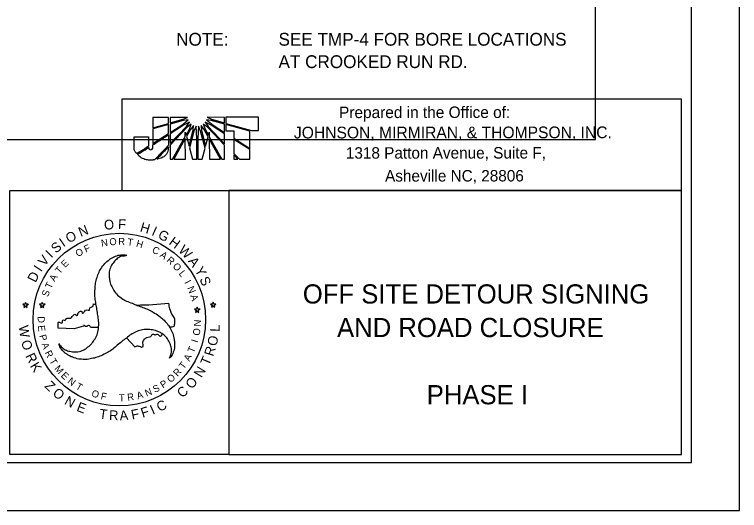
# Model space of a CAD drawing. Extents: x 1613335 to 1618399, y 897277 to 901877.
# Drawn here: x 1617265 to 1618399, y 898577 to 899353 of the extents above; entities that cross this region are included whole.
import ezdxf

# ---------------------------------------------------------------- set-up
doc = ezdxf.new("R2010")
doc.units = 0
for name, color, linetype in [('Default', 7, 'Continuous'), ('DEV BORDER CELL', 7, 'Continuous'), ('DEV DOT SWIRL SEAL CELL', 7, 'Continuous'), ('Scratch_Level_0', 7, 'Continuous'), ('Sheet Plan CELL', 7, 'Continuous'), ('Sheet Plot Border Outside CELL', 7, 'Continuous'), ('Sheet Title CELL', 7, 'Continuous'), ('Text', 7, 'Continuous'), ('WZ INSETA CELL', 7, 'Continuous')]:
    doc.layers.add(name, color=color, linetype=linetype)

msp = doc.modelspace()

# ---------------------------------------------------------------- linework, layer by layer
at = {"layer": 'Default'}
for p, q in [((1617505.8, 899191.7), (1617481.5, 899191.7)), ((1617481.5, 899191.7), (1617481.6, 899175.6)), ((1617505.8, 899182.3), (1617505.8, 899191.7)), ((1617535.7, 899191.8), (1617508.3, 899191.8)), ((1617508.3, 899191.8), (1617508.4, 899183.1)), ((1617528.7, 899188.7), (1617535.7, 899191.8)), ((1617593.6, 899191.8), (1617566.6, 899191.9)), ((1617566.6, 899191.9), (1617573.4, 899188.7)), ((1617593.6, 899183), (1617593.6, 899191.8)), ((1617646.5, 899191.9), (1617595.4, 899191.9)), ((1617595.4, 899191.9), (1617595.5, 899182.5)), ((1617646.5, 899171), (1617646.5, 899191.9)), ((1617481.6, 899175.6), (1617505.8, 899182.3)), ((1617505.8, 899180.5), (1617481.6, 899173.7)), ((1617505.8, 899166.5), (1617505.8, 899180.5)), ((1617508.4, 899183.1), (1617528.7, 899188.7)), ((1617528.7, 899186.9), (1617508.4, 899181.2)), ((1617508.4, 899181.2), (1617508.4, 899168.1)), ((1617508.4, 899168.1), (1617526.6, 899179.6)), ((1617526.6, 899179.6), (1617536.7, 899187.8)), ((1617536.7, 899187.8), (1617528.7, 899186.9)), ((1617538.7, 899184.1), (1617529.4, 899179.4)), ((1617534, 899177.5), (1617538.7, 899184.1)), ((1617541.5, 899181.1), (1617535, 899176.2)), ((1617538.5, 899173.4), (1617541.5, 899181.1)), ((1617560.3, 899181.2), (1617563.3, 899173.4)), ((1617566.8, 899176.2), (1617560.3, 899181.2)), ((1617563.1, 899184.1), (1617567.8, 899177.4)), ((1617572.5, 899179.4), (1617563.1, 899184.1)), ((1617565.3, 899187.9), (1617575.5, 899179.5)), ((1617572.8, 899186.9), (1617565.3, 899187.9)), ((1617593.6, 899181.2), (1617572.8, 899186.9)), ((1617573.4, 899188.7), (1617593.6, 899183)), ((1617593.4, 899168.3), (1617593.6, 899181.2)), ((1617595.5, 899182.5), (1617595.5, 899182.2)), ((1617595.5, 899182.2), (1617635.7, 899171)), ((1617595.5, 899180.8), (1617595.5, 899180.6)), ((1617633.1, 899170.1), (1617595.5, 899180.8)), ((1617595.5, 899180.6), (1617595.5, 899170.8)), ((1617481.6, 899173.7), (1617481.6, 899151.1)), ((1617529.4, 899179.4), (1617508.4, 899166)), ((1617508.4, 899150.8), (1617534, 899177.5)), ((1617535, 899176.2), (1617508.4, 899148.2)), ((1617532.2, 899162.1), (1617532.2, 899168.5)), ((1617532.2, 899168.5), (1617533.4, 899164.1)), ((1617533.4, 899164.1), (1617538.5, 899173.4)), ((1617540.2, 899172.8), (1617534.1, 899161.8)), ((1617538, 899147.2), (1617544.3, 899171.5)), ((1617545.6, 899170.1), (1617538.8, 899143.9)), ((1617545, 899179), (1617540.2, 899172.8)), ((1617544.3, 899171.5), (1617545, 899179)), ((1617549, 899177.9), (1617545.6, 899170.1)), ((1617550, 899158.7), (1617549, 899177.9)), ((1617553, 899177.9), (1617551.7, 899158.7)), ((1617556.2, 899170.1), (1617553, 899177.9)), ((1617563.2, 899143.5), (1617556.2, 899170.1)), ((1617556.9, 899179), (1617557.7, 899171.2)), ((1617561.6, 899172.8), (1617556.9, 899179)), ((1617557.7, 899171.2), (1617564, 899146.7)), ((1617567.9, 899161.4), (1617561.6, 899172.8)), ((1617563.3, 899173.4), (1617568.5, 899163.7)), ((1617593.4, 899148.1), (1617566.8, 899176.2)), ((1617567.8, 899177.4), (1617593.4, 899150.6)), ((1617568.5, 899163.7), (1617569.7, 899168.5)), ((1617569.7, 899168.5), (1617569.7, 899161.4)), ((1617593.4, 899166.2), (1617572.5, 899179.4)), ((1617575.5, 899179.5), (1617593.4, 899168.3)), ((1617595.5, 899170.8), (1617607.9, 899170.9)), ((1617607.9, 899170.9), (1617607.9, 899159.2)), ((1617633.1, 899143.3), (1617633.1, 899170.1)), ((1617635.7, 899171), (1617646.5, 899171)), ((1617481.6, 899151.1), (1617505.8, 899166.5)), ((1617508.4, 899166), (1617508.4, 899150.8)), ((1617512.4, 899126.2), (1617532.2, 899162.1)), ((1617532.2, 899158.6), (1617514.3, 899126.2)), ((1617532.4, 899126.2), (1617532.2, 899158.6)), ((1617534.1, 899161.8), (1617538, 899147.2)), ((1617550.1, 899126.4), (1617550, 899158.7)), ((1617551.7, 899158.7), (1617551.8, 899126.4)), ((1617564, 899146.7), (1617567.9, 899161.4)), ((1617569.7, 899161.4), (1617589.2, 899126.3)), ((1617587.2, 899126.4), (1617569.7, 899158)), ((1617569.7, 899158), (1617569.8, 899126.4)), ((1617593.4, 899150.6), (1617593.4, 899166.2)), ((1617607.9, 899159.2), (1617633.1, 899143.3)), ((1617607.9, 899157.2), (1617608, 899135.5)), ((1617633.1, 899141.4), (1617607.9, 899157.2)), ((1617508.4, 899148.2), (1617508.4, 899126.2)), ((1617593.5, 899126.3), (1617593.4, 899148.1)), ((1617538.8, 899143.9), (1617543.4, 899126.4)), ((1617558.5, 899126.4), (1617563.2, 899143.5)), ((1617608, 899135.5), (1617616.7, 899126.3)), ((1617633.1, 899126.3), (1617633.1, 899141.4)), ((1617508.4, 899126.2), (1617512.4, 899126.2)), ((1617514.3, 899126.2), (1617532.4, 899126.2)), ((1617543.4, 899126.4), (1617550.1, 899126.4)), ((1617551.8, 899126.4), (1617558.5, 899126.4)), ((1617569.8, 899126.4), (1617587.2, 899126.4)), ((1617589.2, 899126.3), (1617593.5, 899126.3)), ((1617614.3, 899126.3), (1617608, 899133.1)), ((1617608, 899133.1), (1617608, 899126.3)), ((1617608, 899126.3), (1617614.3, 899126.3)), ((1617616.7, 899126.3), (1617633.1, 899126.3))]:
    msp.add_line(p, q, dxfattribs=at)
for points in [[(1617481.6, 899175.6), (1617505.8, 899182.3), (1617505.8, 899191.7), (1617481.5, 899191.7), (1617481.6, 899175.6)], [(1617528.7, 899188.7), (1617535.7, 899191.8), (1617508.3, 899191.8), (1617508.4, 899183.1), (1617528.7, 899188.7)], [(1617573.4, 899188.7), (1617593.6, 899183), (1617593.6, 899191.8), (1617566.6, 899191.9), (1617573.4, 899188.7)], [(1617481.6, 899151.1), (1617505.8, 899166.5), (1617505.8, 899180.5), (1617481.6, 899173.7), (1617481.6, 899151.1)], [(1617508.4, 899181.2), (1617508.4, 899168.1), (1617526.6, 899179.6), (1617536.7, 899187.8), (1617528.7, 899186.9), (1617508.4, 899181.2)], [(1617508.4, 899166), (1617508.4, 899150.8), (1617534, 899177.5), (1617538.7, 899184.1), (1617529.4, 899179.4), (1617508.4, 899166)], [(1617541.5, 899181.1), (1617535, 899176.2), (1617508.4, 899148.2), (1617508.4, 899126.2), (1617512.4, 899126.2), (1617532.2, 899162.1), (1617532.2, 899168.5), (1617533.4, 899164.1), (1617538.5, 899173.4), (1617541.5, 899181.1)], [(1617560.3, 899181.2), (1617563.3, 899173.4), (1617568.5, 899163.7), (1617569.7, 899168.5), (1617569.7, 899161.4), (1617589.2, 899126.3), (1617593.5, 899126.3), (1617593.4, 899148.1), (1617566.8, 899176.2), (1617560.3, 899181.2)], [(1617563.1, 899184.1), (1617567.8, 899177.4), (1617593.4, 899150.6), (1617593.4, 899166.2), (1617572.5, 899179.4), (1617563.1, 899184.1)], [(1617565.3, 899187.9), (1617575.5, 899179.5), (1617593.4, 899168.3), (1617593.6, 899181.2), (1617572.8, 899186.9), (1617565.3, 899187.9)], [(1617595.5, 899180.8), (1617595.5, 899180.6), (1617595.5, 899170.8), (1617607.9, 899170.9), (1617607.9, 899159.2), (1617633.1, 899143.3), (1617633.1, 899170.1), (1617595.5, 899180.8)], [(1617545, 899179), (1617540.2, 899172.8), (1617534.1, 899161.8), (1617538, 899147.2), (1617544.3, 899171.5), (1617545, 899179)], [(1617545.6, 899170.1), (1617538.8, 899143.9), (1617543.4, 899126.4), (1617550.1, 899126.4), (1617550, 899158.7), (1617549, 899177.9), (1617545.6, 899170.1)], [(1617553, 899177.9), (1617551.7, 899158.7), (1617551.8, 899126.4), (1617558.5, 899126.4), (1617563.2, 899143.5), (1617556.2, 899170.1), (1617553, 899177.9)], [(1617556.9, 899179), (1617557.7, 899171.2), (1617564, 899146.7), (1617567.9, 899161.4), (1617561.6, 899172.8), (1617556.9, 899179)], [(1617514.3, 899126.2), (1617532.4, 899126.2), (1617532.2, 899158.6), (1617514.3, 899126.2)], [(1617569.8, 899126.4), (1617587.2, 899126.4), (1617569.7, 899158), (1617569.8, 899126.4)], [(1617607.9, 899157.2), (1617608, 899135.5), (1617616.7, 899126.3), (1617633.1, 899126.3), (1617633.1, 899141.4), (1617607.9, 899157.2), (1617607.9, 899157.2)], [(1617608, 899126.3), (1617608, 899126.3), (1617614.3, 899126.3), (1617608, 899133.1), (1617608, 899126.3)]]:
    msp.add_lwpolyline(points, dxfattribs=at)
for points in [[(1617474.6, 899161.5), (1617474.6, 899161.5), (1617452.1, 899161.5), (1617452.1, 899161.5), (1617452.1, 899161.5), (1617452.1, 899147.4), (1617452.1, 899147.4), (1617452.1, 899147.4), (1617452.1, 899145.9), (1617452.1, 899145.9), (1617452.1, 899141.5), (1617453.6, 899138), (1617456.1, 899135.1), (1617456.1, 899135.1), (1617474.6, 899146.3), (1617474.6, 899146.6), (1617474.6, 899146.6), (1617474.6, 899161.5), (1617474.6, 899161.5)], [(1617474.6, 899161.5), (1617474.6, 899161.5), (1617452.1, 899161.5), (1617452.1, 899161.5), (1617452.1, 899161.5), (1617452.1, 899147.4), (1617452.1, 899147.4), (1617452.1, 899147.4), (1617452.1, 899145.9), (1617452.1, 899145.9), (1617452.1, 899141.5), (1617453.6, 899138), (1617456.1, 899135.1), (1617456.1, 899135.1), (1617474.6, 899146.3), (1617474.6, 899146.6), (1617474.6, 899146.6), (1617474.6, 899161.5), (1617474.6, 899161.5)], [(1617478.1, 899141.2), (1617476.7, 899141.2), (1617475.4, 899142), (1617474.9, 899144.7), (1617474.9, 899144.7), (1617457.5, 899133.9), (1617457.5, 899133.9), (1617462.8, 899128.3), (1617471.4, 899124.9), (1617478.7, 899124.9), (1617480.6, 899124.9), (1617482, 899125.1), (1617484, 899125.5), (1617484, 899125.5), (1617505.9, 899148.1), (1617505.9, 899148.1), (1617505.9, 899148.1), (1617505.8, 899164.5), (1617505.8, 899164.5), (1617505.8, 899164.5), (1617481.6, 899149), (1617481.6, 899149), (1617481.6, 899142.9), (1617480.1, 899141.2), (1617478.1, 899141.2)], [(1617478.1, 899141.2), (1617476.7, 899141.2), (1617475.4, 899142), (1617474.9, 899144.7), (1617474.9, 899144.7), (1617457.5, 899133.9), (1617457.5, 899133.9), (1617462.8, 899128.3), (1617471.4, 899124.9), (1617478.7, 899124.9), (1617480.6, 899124.9), (1617482, 899125.1), (1617484, 899125.5), (1617484, 899125.5), (1617505.9, 899148.1), (1617505.9, 899148.1), (1617505.9, 899148.1), (1617505.8, 899164.5), (1617505.8, 899164.5), (1617505.8, 899164.5), (1617481.6, 899149), (1617481.6, 899149), (1617481.6, 899142.9), (1617480.1, 899141.2), (1617478.1, 899141.2)], [(1617505.9, 899145.6), (1617505.9, 899145.6), (1617487, 899126), (1617487, 899126), (1617496.2, 899128.3), (1617505.4, 899134.5), (1617505.9, 899145.6)], [(1617505.9, 899145.6), (1617505.9, 899145.6), (1617487, 899126), (1617487, 899126), (1617496.2, 899128.3), (1617505.4, 899134.5), (1617505.9, 899145.6)]]:
    msp.add_open_spline(points, degree=3, dxfattribs=at)
at = {"layer": 'DEV BORDER CELL'}
for points in [[(1618323.6, 901802.3), (1613823.6, 901802.3), (1613823.6, 898652.3), (1618323.6, 898652.3)], [(1617258.1, 899077.6), (1617600.1, 899077.6), (1617600.1, 898665.1), (1617258.1, 898665.1)], [(1618308.1, 899077.6), (1617600.1, 899077.6), (1617600.1, 898665.1), (1618308.1, 898665.1)]]:
    msp.add_lwpolyline(points, close=True, dxfattribs=at)
at = {"layer": 'DEV DOT SWIRL SEAL CELL'}
for p, q in [((1617278.3, 898899.6), (1617280.9, 898897.7)), ((1617281.6, 898899.6), (1617278.3, 898899.6)), ((1617280.9, 898897.7), (1617280, 898894.6)), ((1617280, 898894.6), (1617282.5, 898896.5)), ((1617282.5, 898902.6), (1617281.6, 898899.6)), ((1617283.6, 898899.6), (1617282.5, 898902.6)), ((1617282.5, 898896.5), (1617285.2, 898894.6)), ((1617282.5, 898896.5), (1617285.2, 898894.6)), ((1617286.8, 898899.6), (1617283.6, 898899.6)), ((1617284.2, 898897.7), (1617286.9, 898899.6)), ((1617284.2, 898897.7), (1617286.8, 898899.6)), ((1617285.2, 898894.6), (1617284.2, 898897.7)), ((1617285.2, 898894.6), (1617284.2, 898897.7)), ((1617307.6, 898899.6), (1617304.3, 898899.6)), ((1617304.3, 898899.6), (1617307, 898897.6)), ((1617307, 898897.6), (1617306, 898894.5)), ((1617306, 898894.5), (1617308.6, 898896.4)), ((1617308.6, 898902.6), (1617307.6, 898899.6)), ((1617309.6, 898899.6), (1617308.6, 898902.6)), ((1617308.6, 898896.4), (1617311.2, 898894.5)), ((1617312.9, 898899.6), (1617309.6, 898899.6)), ((1617310.2, 898897.6), (1617312.9, 898899.6)), ((1617311.2, 898894.5), (1617310.2, 898897.6)), ((1617574.7, 898900), (1617571.5, 898900)), ((1617571.5, 898900), (1617574.1, 898898.1)), ((1617574.1, 898898.1), (1617573.2, 898895)), ((1617573.2, 898895), (1617575.7, 898896.9)), ((1617575.7, 898903), (1617574.7, 898900)), ((1617576.8, 898900), (1617575.7, 898903)), ((1617575.7, 898896.9), (1617578.3, 898895)), ((1617580, 898900), (1617576.8, 898900)), ((1617577.4, 898898.1), (1617580, 898900)), ((1617578.3, 898895), (1617577.4, 898898.1)), ((1617549.9, 898892.1), (1617546.6, 898892.1)), ((1617546.6, 898892.1), (1617549.3, 898890.2)), ((1617549.3, 898890.2), (1617548.3, 898887)), ((1617548.3, 898887), (1617550.9, 898889)), ((1617550.9, 898895.1), (1617549.9, 898892.1)), ((1617551.9, 898892.1), (1617550.9, 898895.1)), ((1617550.9, 898889), (1617553.5, 898887)), ((1617555.2, 898892.1), (1617551.9, 898892.1)), ((1617552.5, 898890.2), (1617555.2, 898892.1)), ((1617553.5, 898887), (1617552.5, 898890.2)), ((1617333.3, 898862.3), (1617333.5, 898870.2)), ((1617358.5, 898861.3), (1617333.3, 898862.3)), ((1617372.9, 898865.6), (1617358.5, 898861.3)), ((1617384, 898863.9), (1617396.6, 898863.8)), ((1617440.2, 898847), (1617453.1, 898833))]:
    msp.add_line(p, q, dxfattribs=at)
for start, end in [(265.6785, 265.9762), (271.2035, 275.3236)]:
    msp.add_arc((1617441.4, 899597.8), 699.6, start, end, dxfattribs=at)
for points in [[(1617334.5, 898837.9), (1617339.7, 898831.9), (1617346.3, 898827.7), (1617353.8, 898825.8), (1617362.2, 898825.3), (1617370.8, 898827.3), (1617376.6, 898830.2), (1617379, 898832.1), (1617383.2, 898835.4), (1617386.1, 898838.7), (1617391.1, 898845.8), (1617395, 898854.1), (1617396.6, 898863.7), (1617396.7, 898864.5), (1617396.6, 898873.5), (1617395.4, 898882.6), (1617394.1, 898891.4), (1617392.5, 898900.5), (1617391.1, 898909.5), (1617390.9, 898918.3), (1617391.5, 898928.4), (1617392.9, 898937), (1617395.7, 898945.9), (1617397.3, 898950), (1617399.3, 898953.4), (1617404.6, 898961.4), (1617411.4, 898967.8), (1617415.9, 898971.2), (1617420.2, 898973.5), (1617420.9, 898973.9), (1617429.5, 898976.6), (1617437.8, 898976.9), (1617440.7, 898976.2)], [(1617440.9, 898976.5), (1617440.7, 898976.2), (1617432.9, 898974.8), (1617425.9, 898971.1), (1617420.5, 898965.7), (1617415.9, 898958.7), (1617413.4, 898950.1), (1617413, 898943.8), (1617413.5, 898940.7), (1617414.2, 898935.4), (1617415.5, 898931.2), (1617419.2, 898923.4), (1617424.5, 898915.8), (1617432, 898909.6), (1617432.7, 898909.1), (1617440.4, 898904.7), (1617449, 898901.2), (1617457.2, 898897.9), (1617465.9, 898894.8), (1617474.4, 898891.4), (1617482.1, 898887.2), (1617490.6, 898881.7), (1617497.3, 898876.2), (1617503.6, 898869.4), (1617506.5, 898865.9), (1617508.3, 898862.4), (1617512.7, 898853.9), (1617514.7, 898844.7), (1617515.5, 898839.1), (1617515.3, 898834.2), (1617515.3, 898833.4), (1617513.3, 898824.7), (1617509.4, 898817.3), (1617507.4, 898815.2)], [(1617333.5, 898870.2), (1617333.3, 898871), (1617334.6, 898871.9), (1617338.4, 898870.3), (1617340.2, 898871.9), (1617340.1, 898873.6), (1617341.7, 898875.2), (1617344.2, 898874.7), (1617346.5, 898877.5), (1617348.6, 898878.1), (1617353.1, 898878.1), (1617358.5, 898883.5), (1617360.7, 898883.8), (1617361.3, 898882.4), (1617362.6, 898882.1), (1617365, 898886.5), (1617365.6, 898887.1), (1617369.6, 898888.8), (1617370.7, 898888), (1617371.1, 898886), (1617371.7, 898885.7), (1617373, 898886.6), (1617374.9, 898889), (1617378.3, 898890.8), (1617382.2, 898890.3), (1617382.9, 898893.5), (1617387.4, 898896.5), (1617388.4, 898898.4), (1617388.6, 898900.3)], [(1617507.2, 898864.6), (1617514.6, 898865.5), (1617515.7, 898871.4), (1617515.8, 898876.3), (1617512.7, 898881.9), (1617508.2, 898892.4), (1617506.3, 898901.3)], [(1617384, 898863.9), (1617383, 898865.8), (1617380.9, 898866.4), (1617378.1, 898865), (1617376.1, 898865.1), (1617373.8, 898866.8), (1617372.9, 898865.6)], [(1617507.4, 898815.2), (1617510, 898822.6), (1617510.4, 898830.5), (1617508.3, 898837.9), (1617504.5, 898845.4), (1617498.5, 898851.9), (1617493.2, 898855.4), (1617490.2, 898856.5), (1617485.4, 898858.6), (1617480.9, 898859.5), (1617472.4, 898860.2), (1617463.1, 898859.4), (1617454, 898856), (1617453.3, 898855.7), (1617445.6, 898851.1), (1617438.2, 898845.5), (1617431.2, 898840), (1617424.2, 898834.1), (1617417.1, 898828.3), (1617409.6, 898823.8), (1617400.6, 898819.2), (1617392.4, 898816.2), (1617383.4, 898814.2), (1617378.9, 898813.4), (1617374.9, 898813.5), (1617365.5, 898814), (1617356.4, 898816.8), (1617351.3, 898818.9), (1617347.2, 898821.6), (1617346.4, 898822), (1617339.8, 898828), (1617335.4, 898835.1), (1617334.5, 898837.9)], [(1617453.1, 898833), (1617458.2, 898834.6), (1617462.5, 898832.9), (1617464.5, 898832.6), (1617466.2, 898833.9), (1617465.7, 898840.2), (1617467.1, 898843.2), (1617474, 898848.3), (1617478.2, 898849.2), (1617481.4, 898853.1), (1617482.6, 898853), (1617484.6, 898851.9), (1617488.9, 898852.8), (1617492.4, 898850), (1617494.4, 898850.2), (1617496.1, 898853.3)]]:
    msp.add_spline(points, degree=3, dxfattribs=at)
at = {"layer": 'Scratch_Level_0'}
msp.add_lwpolyline([(1618173.6, 901652.3), (1613973.6, 901652.3), (1613973.6, 898802.3), (1616610.1, 898802.3), (1616610.1, 899157.1), (1618173.6, 899157.1)], close=True, dxfattribs=at)
at = {"layer": 'Sheet Plan CELL'}
msp.add_lwpolyline([(1618308.1, 899220.2), (1617433.1, 899220.2), (1617433.1, 899077.6), (1618308.1, 899077.6)], close=True, dxfattribs=at)
at = {"layer": 'Sheet Plot Border Outside CELL'}
msp.add_lwpolyline([(1613334.6, 898577.3), (1618398.6, 898577.3), (1618398.6, 901877.3), (1613334.6, 901877.3)], close=True, dxfattribs=at)
at = {"layer": 'Text'}
msp.add_circle((1617429.1, 898875.7), 134.9, dxfattribs=at)

# ---------------------------------------------------------------- texts
at = {"layer": 'Default'}
for s, p in [('OFF SITE DETOUR SIGNING', (1617715.9, 898900.8)), ('AND ROAD CLOSURE', (1617769.4, 898848.3)), ('PHASE I', (1617909.6, 898743.3))]:
    msp.add_text(s, height=30, dxfattribs=at).set_placement(p)
at = {"layer": 'DEV DOT SWIRL SEAL CELL'}
for s, height, rotation, p in [('F', 15.1, 357.2575, (1617426.8, 899017.6)), ('N', 15.1, 21.5861, (1617368.7, 899004.7)), ('O', 15.1, 5.7649, (1617405.9, 899015.9)), ('H', 15.1, 343.454, (1617460.4, 899013.7)), ('I', 15.1, 335.804, (1617478.4, 899008.1)), ('O', 15.1, 30.0935, (1617350.4, 898994.6)), ('G', 15.1, 331.5167, (1617488.1, 899003.9)), ('I', 15.1, 34.3808, (1617341.7, 898988.5)), ('N', 10.9, 9.0227, (1617401.4, 898989.6)), ('O', 10.9, 3.9446, (1617413.9, 898991.7)), ('R', 10.9, 358.8665, (1617427.3, 898992.6)), ('H', 10.9, 343.6322, (1617454.5, 898990)), ('H', 15.1, 323.4632, (1617505.4, 898994.2)), ('S', 15.1, 40.5848, (1617330.1, 898978.6)), ('F', 10.9, 24.2569, (1617376.8, 898980.2)), ('C', 10.9, 333.4761, (1617479.2, 898981.2)), ('W', 15.1, 315.8133, (1617520.4, 898982.8)), ('V', 15.1, 51.5806, (1617312.4, 898958.1)), ('I', 15.1, 44.8722, (1617322.8, 898971)), ('O', 10.9, 29.335, (1617364.2, 898973.2)), ('A', 10.9, 323.3199, (1617491.5, 898974.8)), ('E', 10.9, 44.5692, (1617344.3, 898956.1)), ('R', 10.9, 318.2418, (1617502, 898967.2)), ('A', 15.1, 306.7762, (1617535.9, 898966.9)), ('I', 15.1, 55.8679, (1617306.7, 898949.3)), ('T', 10.9, 49.6473, (1617335.8, 898946.2)), ('O', 10.9, 313.1637, (1617511.6, 898958.4)), ('L', 10.9, 308.0856, (1617521.3, 898947.4)), ('Y', 15.1, 299.7484, (1617546.2, 898953)), ('D', 15.1, 63.459, (1617298.1, 898932.7)), ('A', 10.9, 59.8035, (1617328.1, 898934.2)), ('S', 15.1, 293.2249, (1617554.1, 898939)), ('T', 10.9, 64.8816, (1617322.3, 898922.9)), ('I', 10.9, 297.9295, (1617530.4, 898933.9)), ('S', 10.9, 69.9597, (1617317.5, 898910.4)), ('N', 10.9, 292.8514, (1617535, 898925.2)), ('A', 10.9, 287.7733, (1617539.8, 898913)), ('D', 10.9, 270.272, (1617301.5, 898880.9)), ('N', 10.9, 87.733, (1617556.4, 898864.8)), ('E', 10.9, 275.3501, (1617301.8, 898866.3)), ('P', 10.9, 285.5063, (1617303.6, 898850.7)), ('O', 10.9, 82.9269, (1617554.6, 898850.2)), ('I', 10.9, 72.7707, (1617551.3, 898838.9)), ('A', 10.9, 290.5843, (1617307.2, 898837.3)), ('T', 10.9, 67.6926, (1617545.3, 898822.7)), ('R', 10.9, 295.6624, (1617312.2, 898824.3)), ('A', 10.9, 62.6145, (1617538.6, 898809.7)), ('T', 10.9, 300.7405, (1617319.1, 898811.1)), ('T', 10.9, 52.4584, (1617529.8, 898797.3)), ('M', 10.9, 310.8967, (1617326.9, 898798.8)), ('E', 10.9, 315.9748, (1617336.9, 898787.3)), ('R', 10.9, 47.3803, (1617520, 898786)), ('N', 10.9, 321.0529, (1617347.2, 898777.8)), ('O', 10.9, 42.3022, (1617509.4, 898776.3)), ('T', 10.9, 331.209, (1617359.9, 898768.1)), ('S', 10.9, 27.068, (1617484.8, 898760.9)), ('P', 10.9, 32.146, (1617497.2, 898767.8)), ('O', 10.9, 341.3652, (1617384.6, 898756.1)), ('F', 10.9, 346.4433, (1617399.3, 898751.6)), ('R', 10.9, 6.7556, (1617442.1, 898748.8)), ('A', 10.9, 16.9118, (1617457.9, 898751.1)), ('N', 10.9, 21.9899, (1617471.6, 898755.2)), ('T', 10.9, 1.6775, (1617428.6, 898748))]:
    msp.add_text(s, height=height, rotation=rotation, dxfattribs=at).set_placement(p)
at = {"layer": 'Sheet Title CELL'}
for s, height, p in [('Prepared in the Office of:', 17.996, (1617772.6, 899190.6)), ('JOHNSON, MIRMIRAN, & THOMPSON, INC.', 18.279, (1617702, 899158.8)), ('1318 Patton Avenue, Suite F,', 17.904, (1617783.2, 899127.2)), ('Asheville NC, 28806', 17.904, (1617844.5, 899091.4))]:
    msp.add_text(s, height=height, rotation=0.0516, dxfattribs=at).set_placement(p)
at = {"layer": 'Text'}
for s, height, rotation, p in [('T', 10.9, 353.7884, (1617441.2, 898991.9)), ('W', 15.1, 278.15, (1617271.7, 898865.6)), ('L', 15.1, 87.429, (1617585.7, 898856.4)), ('O', 15.1, 287.1147, (1617275.2, 898841.2)), ('O', 15.1, 78.9896, (1617581.2, 898833.6)), ('R', 15.1, 72.7519, (1617575.7, 898817.3)), ('R', 15.1, 295.5541, (1617281.9, 898819)), ('T', 15.1, 66.881, (1617569, 898802.7)), ('K', 15.1, 301.7918, (1617288.9, 898803.3)), ('N', 15.1, 58.892, (1617557.4, 898783.9)), ('O', 15.1, 50.4526, (1617542.6, 898766.1)), ('Z', 15.1, 316.1688, (1617311.3, 898770.8)), ('O', 15.1, 322.5233, (1617323.6, 898758.4)), ('C', 15.1, 43.0807, (1617527.6, 898752.4)), ('N', 15.1, 330.9626, (1617342, 898744.2)), ('C', 15.1, 28.0033, (1617492.1, 898731.1)), ('E', 15.1, 338.9517, (1617361.1, 898733.4)), ('F', 15.1, 17.7627, (1617465.4, 898722.2)), ('I', 15.1, 23.7503, (1617481.2, 898726.8)), ('T', 15.1, 352.6948, (1617396.9, 898721.3)), ('R', 15.1, 358.5656, (1617412.9, 898718.8)), ('A', 15.1, 4.8034, (1617430, 898718)), ('F', 15.1, 11.7751, (1617449.2, 898719.2))]:
    msp.add_text(s, height=height, rotation=rotation, dxfattribs=at).set_placement(p)
at = {"layer": 'WZ INSETA CELL'}
for s, p in [('NOTE:', (1617517.9, 899303.8)), ('SEE TMP-4 FOR BORE LOCATIONS', (1617677.9, 899303.8)), ('AT CROOKED RUN RD.', (1617677.9, 899268.8))]:
    msp.add_text(s, height=20, dxfattribs=at).set_placement(p)

doc.saveas('drawing.dxf')
